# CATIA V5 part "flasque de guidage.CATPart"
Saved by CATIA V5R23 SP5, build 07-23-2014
Part number: flasque de guidage
Definition: flasque de guidage
Source: made
Bounding box of the stored display mesh (mm): x -45 to 0, y -54.95 to 54.95, z -55 to 55
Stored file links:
  C:\wamp\www\COURS\CONCEPTION GMP1\TITRE 01-CATIA VOLUMIQUE\05--ACTIONNEUR DE VANNE\prof\CORRECTION\Assemblage\flasque de guidage.CATPart
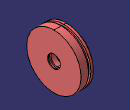
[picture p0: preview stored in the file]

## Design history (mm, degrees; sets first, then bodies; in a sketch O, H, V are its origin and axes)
Body1 "NONE" (main body)
  Solid1 "Manifold Solid #7876": solid without history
